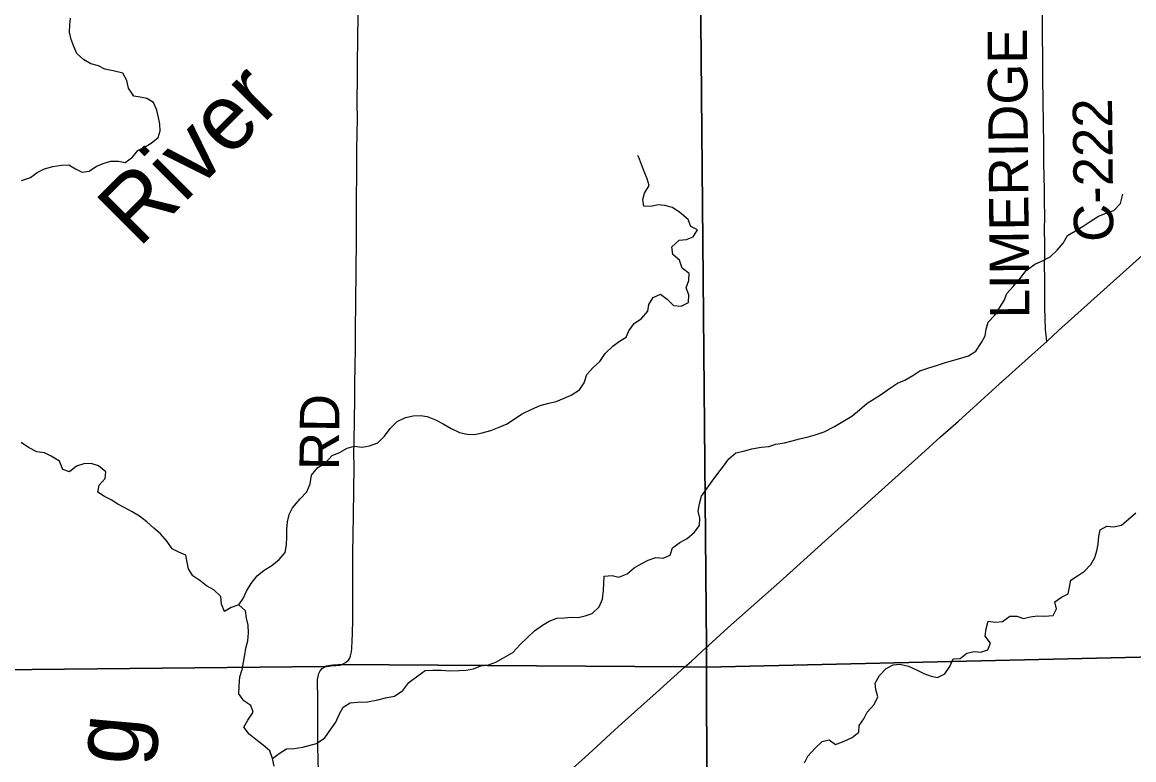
# Model space of a CAD drawing. Extents: x 0 to 34, y 0 to 22.
# Drawn here: x 26.924 to 28.527, y 12.614 to 13.678 of the extents above; entities that cross this region are included whole.
import ezdxf

# ---------------------------------------------------------------- set-up
doc = ezdxf.new("R2010")
doc.units = 0
for name, color, linetype in [('GM_X_Corporation', 7, 'Continuous'), ('GM_X_County_Road', 7, 'Continuous'), ('GM_X_County_Road_Text', 7, 'Continuous'), ('GM_X_Minor_River', 7, 'Continuous'), ('GM_X_Minor_River_Text', 7, 'Continuous'), ('GM_X_State_Route', 7, 'Continuous'), ('GM_X_Township_Road', 7, 'Continuous'), ('GM_X_Township_Road_Text', 7, 'Continuous')]:
    doc.layers.add(name, color=color, linetype=linetype)

msp = doc.modelspace()

# ---------------------------------------------------------------- linework, layer by layer
at = {"layer": 'GM_X_Corporation'}
for points in [[(26.7975, 12.7429), (27.3609, 12.7486), (27.363, 12.7493), (27.3691, 12.7502), (27.3721, 12.7505), (27.377, 12.7508), (27.3825, 12.7513), (27.879, 12.748), (27.9112, 12.7478), (27.9109, 12.7769), (27.9019, 13.7865), (27.8823, 15.2828), (27.8801, 15.6288), (27.88, 15.6409), (27.8849, 16.5038), (27.8821, 16.7067), (23.0715, 16.7067)], [(27.9019, 13.7865), (27.9109, 12.7769), (27.9112, 12.7478), (28.7651, 12.7673)], [(28.7651, 12.7673), (27.9112, 12.7478), (27.9132, 12.0667)], [(27.9132, 12.0667), (27.9112, 12.7478), (27.879, 12.748), (27.3825, 12.7513), (27.377, 12.7508), (27.3721, 12.7505), (27.3691, 12.7502), (27.363, 12.7493), (27.3609, 12.7486), (26.7975, 12.7429)]]:
    msp.add_lwpolyline(points, dxfattribs=at)
at = {"layer": 'GM_X_County_Road'}
msp.add_lwpolyline([(28.402, 13.2172), (28.4007, 13.2265), (28.3999, 13.2346), (28.3993, 13.2511), (28.399, 13.266), (28.3989, 13.2847), (28.3987, 13.3002), (28.3987, 13.307), (28.3986, 13.3282), (28.3987, 13.3412), (28.3988, 13.3586), (28.3986, 13.3784), (28.3988, 13.3975), (28.3986, 13.4198), (28.3983, 13.4359), (28.3977, 13.475), (28.3975, 13.4886), (28.3975, 13.5017), (28.3966, 13.5629), (28.396, 13.5979), (28.3958, 13.6141), (28.3957, 13.6713), (28.3952, 13.7432)], dxfattribs=at)
at = {"layer": 'GM_X_Minor_River'}
for points in [[(27.1006, 13.4972), (27.1104, 13.5034), (27.1202, 13.5115), (27.1231, 13.521), (27.1226, 13.5305), (27.121, 13.5404), (27.1186, 13.5506), (27.1139, 13.5619), (27.104, 13.5675), (27.0945, 13.5697), (27.0851, 13.5711), (27.0774, 13.5824), (27.0753, 13.5937), (27.0695, 13.6043), (27.0555, 13.6076), (27.0437, 13.6101), (27.0342, 13.6149), (27.0232, 13.6178), (27.0129, 13.6238), (27.0033, 13.6324), (26.999, 13.6426), (26.9951, 13.6528), (26.9927, 13.6634), (26.993, 13.6737), (26.994, 13.6835)], [(26.9235, 13.4496), (26.9364, 13.4539), (26.9461, 13.4608), (26.9567, 13.4663), (26.9684, 13.4695), (26.9812, 13.4715), (26.9915, 13.472), (27.001, 13.4664), (27.0109, 13.4612), (27.0207, 13.4629), (27.0313, 13.4698), (27.0426, 13.4745), (27.0524, 13.4773), (27.0634, 13.477), (27.0729, 13.4752), (27.0834, 13.483), (27.0909, 13.4925), (27.1006, 13.4972)], [(27.2368, 12.8374), (27.2431, 12.8469), (27.2479, 12.8572), (27.2543, 12.8683), (27.2632, 12.8794), (27.2734, 12.8875), (27.2843, 12.8941), (27.2948, 12.903), (27.3037, 12.913), (27.3055, 12.924), (27.3058, 12.9358), (27.306, 12.9468), (27.307, 12.957), (27.3092, 12.9677), (27.314, 12.9776), (27.3252, 12.9903), (27.3346, 13.0006), (27.3394, 13.0121), (27.3415, 13.0243), (27.3505, 13.0354), (27.3618, 13.0424), (27.3711, 13.0527), (27.382, 13.0574), (27.393, 13.0636), (27.4028, 13.0664), (27.4145, 13.065), (27.4251, 13.067), (27.4372, 13.0713), (27.4466, 13.0809), (27.4548, 13.0917), (27.4649, 13.1017), (27.4769, 13.1075), (27.4879, 13.1099), (27.4989, 13.1104), (27.5084, 13.109), (27.5205, 13.1042), (27.5312, 13.0983), (27.543, 13.092), (27.5548, 13.086), (27.5662, 13.0835), (27.5764, 13.0832), (27.5878, 13.0856), (27.5999, 13.0888), (27.6119, 13.0939), (27.6236, 13.0986), (27.6341, 13.1056), (27.6454, 13.1129), (27.659, 13.1199), (27.671, 13.125), (27.6839, 13.1282), (27.6945, 13.1306), (27.7058, 13.1353), (27.7159, 13.1399), (27.728, 13.1477), (27.7347, 13.1576), (27.7383, 13.1698), (27.7477, 13.1798), (27.7574, 13.1886), (27.7649, 13.2001), (27.7758, 13.2105), (27.7855, 13.2178), (27.7953, 13.2233), (27.799, 13.2328), (27.8068, 13.2431), (27.8173, 13.2505), (27.8263, 13.2612), (27.8277, 13.2707), (27.8341, 13.2807), (27.8446, 13.2854), (27.8542, 13.2783), (27.8637, 13.2693), (27.8747, 13.2683), (27.8853, 13.2737), (27.8855, 13.2847), (27.8816, 13.2945), (27.8857, 13.3052), (27.8859, 13.3155), (27.876, 13.3229), (27.8721, 13.3343), (27.8625, 13.3425), (27.8609, 13.3535), (27.8718, 13.3631), (27.882, 13.3644), (27.8918, 13.3683), (27.8981, 13.3783), (27.8886, 13.3831), (27.8847, 13.3933), (27.8725, 13.4034), (27.8621, 13.4105), (27.8511, 13.4134), (27.8413, 13.4141), (27.8307, 13.412), (27.8205, 13.4123), (27.8192, 13.4218), (27.8218, 13.4313), (27.8285, 13.442), (27.8253, 13.4518), (27.821, 13.4624), (27.8171, 13.4722), (27.8128, 13.484), (27.8117, 13.4855)], [(28.2993, 13.2034), (28.3078, 13.2156), (28.313, 13.2256), (28.3144, 13.2351), (28.317, 13.245), (28.3267, 13.2554), (28.3334, 13.2657), (28.3405, 13.2764), (28.3442, 13.2863), (28.3531, 13.2963), (28.3629, 13.3078), (28.3722, 13.3197), (28.3846, 13.3286), (28.3948, 13.3332), (28.4068, 13.3395), (28.4166, 13.3491), (28.4255, 13.3591), (28.4315, 13.3701), (28.4431, 13.3767), (28.454, 13.3837), (28.4642, 13.3903), (28.4762, 13.398), (28.4872, 13.4023), (28.4985, 13.4062), (28.5078, 13.4162), (28.5111, 13.4277), (28.5115, 13.4296)], [(27.2851, 12.6162), (27.2949, 12.6232), (27.3054, 12.6297), (27.3164, 12.6306), (27.3292, 12.6323), (27.3489, 12.6378), (27.3605, 12.6459), (27.3695, 12.6582), (27.3766, 12.6685), (27.3814, 12.6792), (27.3873, 12.6899), (27.3975, 12.6965), (27.4077, 12.697), (27.4224, 12.6979), (27.4372, 12.7008), (27.4481, 12.7035), (27.461, 12.706), (27.4734, 12.7141), (27.482, 12.7256), (27.4947, 12.7352), (27.5056, 12.743), (27.5166, 12.7435), (27.5284, 12.7432), (27.5409, 12.7422), (27.5545, 12.7431), (27.5643, 12.7433), (27.5749, 12.7453), (27.5859, 12.7496), (27.5968, 12.7509), (27.6074, 12.7548), (27.6183, 12.761), (27.6319, 12.7687), (27.6423, 12.7806), (27.6532, 12.7906), (27.6629, 12.7999), (27.6746, 12.8084), (27.6844, 12.8138), (27.6953, 12.8185), (27.7063, 12.8186), (27.7161, 12.8199), (27.726, 12.8192), (27.7362, 12.8216), (27.746, 12.8251), (27.7561, 12.8348), (27.7613, 12.8458), (27.7626, 12.8584), (27.7629, 12.8682), (27.7636, 12.8789), (27.7749, 12.8798), (27.7848, 12.8776), (27.7965, 12.8823), (27.8066, 12.8908), (27.8168, 12.8966), (27.8269, 12.902), (27.8379, 12.9056), (27.8485, 12.9049), (27.8587, 12.9092), (27.8619, 12.9199), (27.8728, 12.9276), (27.883, 12.9334), (27.8935, 12.9419), (27.901, 12.9519), (27.9016, 12.9625), (27.8989, 12.9727), (27.901, 12.9834), (27.9039, 12.9944), (27.9121, 13.0056), (27.9192, 13.0159), (27.9274, 13.027), (27.9356, 13.0377), (27.9435, 13.0481), (27.9532, 13.0565), (27.9645, 13.059), (27.9762, 13.0625), (27.9899, 13.0649), (28.0008, 13.0658), (28.011, 13.069), (28.0235, 13.071), (28.0344, 13.0738), (28.0454, 13.077), (28.0575, 13.0798), (28.0677, 13.0826), (28.0805, 13.0869), (28.0956, 13.0947), (28.1099, 13.1032), (28.1204, 13.1098), (28.1317, 13.1186), (28.1425, 13.1283), (28.1527, 13.1348), (28.1632, 13.1414), (28.1764, 13.1503), (28.1865, 13.1573), (28.1971, 13.1616), (28.2088, 13.1682), (28.2189, 13.1747), (28.2302, 13.179), (28.2442, 13.183), (28.2559, 13.1869), (28.2778, 13.1933), (28.2887, 13.1968), (28.2993, 13.2034)], [(27.2259, 12.8338), (27.2161, 12.828), (27.2118, 12.8386), (27.2109, 12.8496), (27.2006, 12.8593), (27.1899, 12.8649), (27.1804, 12.8728), (27.1704, 12.8795), (27.1643, 12.8893), (27.1623, 12.8991), (27.1602, 12.909), (27.15, 12.9134), (27.1405, 12.9182), (27.1335, 12.9288), (27.1239, 12.9401), (27.114, 12.9483), (27.104, 12.9573), (27.0937, 12.9652), (27.0827, 12.9715), (27.0724, 12.9774), (27.0621, 12.9826), (27.0525, 12.989), (27.043, 12.9938), (27.0335, 12.9998), (27.0353, 13.01), (27.0442, 13.0196), (27.0449, 13.0291), (27.0346, 13.0381), (27.0236, 13.0414), (27.013, 13.0409), (27.0028, 13.0377), (26.9926, 13.0293), (26.9831, 13.0326), (26.9781, 13.0447), (26.9662, 13.0517), (26.9563, 13.0566), (26.9457, 13.0583), (26.9335, 13.0643), (26.9228, 13.0717)], [(28.1527, 12.694), (28.1583, 12.7051), (28.1551, 12.7153), (28.1543, 12.7248), (28.1606, 12.7355), (28.1699, 12.7458), (28.1801, 12.7509), (28.1899, 12.7518), (28.2021, 12.7493), (28.2139, 12.7437), (28.2242, 12.7385), (28.2348, 12.7348), (28.2443, 12.733), (28.2545, 12.7381), (28.2619, 12.7488), (28.2667, 12.7595), (28.2766, 12.7604), (28.2863, 12.7681), (28.2969, 12.7705), (28.3064, 12.7691), (28.3166, 12.7726), (28.3206, 12.7822), (28.3129, 12.7923), (28.3143, 12.803), (28.3172, 12.814), (28.3279, 12.8126), (28.3377, 12.8135), (28.3486, 12.8212), (28.3585, 12.8213), (28.368, 12.8177), (28.3778, 12.8204), (28.3884, 12.8217), (28.3982, 12.8214), (28.4111, 12.8223), (28.4155, 12.8319), (28.4131, 12.8417), (28.4229, 12.8487), (28.4327, 12.8534), (28.4345, 12.8629), (28.4363, 12.8731), (28.446, 12.8793), (28.4562, 12.8859), (28.4652, 12.8959), (28.4711, 12.9058), (28.474, 12.9153), (28.4758, 12.9249), (28.4769, 12.9359), (28.4786, 12.9458), (28.4884, 12.9512), (28.4979, 12.9502), (28.5096, 12.9522), (28.5194, 12.9611), (28.5299, 12.9703)], [(27.2875, 12.6048), (27.2851, 12.6162), (27.2812, 12.6272), (27.2716, 12.6354), (27.2613, 12.6436), (27.2514, 12.6511), (27.2441, 12.6613), (27.2497, 12.6712), (27.2575, 12.6827), (27.254, 12.6925), (27.244, 12.6992), (27.2367, 12.709), (27.2374, 12.7204), (27.238, 12.7337), (27.2413, 12.7444), (27.2434, 12.7547), (27.2452, 12.7653), (27.2466, 12.7752), (27.2495, 12.7855), (27.2505, 12.7973), (27.2504, 12.8083), (27.2476, 12.8185), (27.2464, 12.8287), (27.2368, 12.8374), (27.2259, 12.8338)], [(28.0525, 12.6097), (28.0573, 12.6196), (28.0674, 12.6303), (28.0779, 12.6407), (28.0878, 12.6431), (28.0973, 12.6364), (28.1094, 12.6411), (28.121, 12.6465), (28.1308, 12.6539), (28.1311, 12.6634), (28.1378, 12.6733), (28.1426, 12.6829), (28.1527, 12.694)]]:
    msp.add_lwpolyline(points, dxfattribs=at)
at = {"layer": 'GM_X_State_Route'}
msp.add_line((27.9111, 12.7764), (27.9134, 12.7784), dxfattribs=at)
for points in [[(27.9134, 12.7784), (27.9425, 12.8048), (28.0163, 12.8703), (28.0564, 12.9065), (28.0822, 12.9299), (28.1233, 12.967), (28.1543, 12.9947), (28.1926, 13.0293), (28.2212, 13.0546), (28.2487, 13.0796), (28.2746, 13.1026), (28.3064, 13.1315), (28.3331, 13.1557), (28.3803, 13.1979), (28.402, 13.2172), (28.4187, 13.2331), (28.5256, 13.329), (28.6314, 13.424), (28.6966, 13.4835), (28.793, 13.5705), (28.8606, 13.6316), (28.8818, 13.6509), (28.9186, 13.6843)], [(27.8792, 12.7475), (27.8892, 12.7565), (27.9111, 12.7764)], [(27.6966, 12.5826), (27.7354, 12.6175), (27.7588, 12.6388), (27.7726, 12.6514), (27.7897, 12.6668), (27.8386, 12.7109), (27.8792, 12.7475)]]:
    msp.add_lwpolyline(points, dxfattribs=at)
at = {"layer": 'GM_X_Township_Road'}
for points in [[(27.3827, 12.7508), (27.3873, 12.7526), (27.3905, 12.7542), (27.395, 12.7577), (27.3966, 12.7606), (27.3979, 12.7642), (27.3991, 12.7698), (27.3997, 12.7748), (27.4, 12.7861), (27.4004, 12.7954), (27.4009, 12.8171), (27.401, 12.8314), (27.4009, 12.8582), (27.4011, 12.8737), (27.4011, 12.888), (27.4011, 12.8979), (27.4012, 12.9028), (27.4013, 12.9078), (27.4013, 12.9115), (27.4014, 12.9401), (27.4019, 12.9649), (27.4025, 13.0042), (27.403, 13.0357), (27.4026, 13.0569), (27.4028, 13.0718), (27.4034, 13.1053), (27.4039, 13.1328), (27.4042, 13.1576), (27.4045, 13.1796), (27.4048, 13.2091), (27.4049, 13.2447), (27.4052, 13.2628), (27.4054, 13.2826), (27.406, 13.3105), (27.4061, 13.3282), (27.4063, 13.3542), (27.4066, 13.3718), (27.4066, 13.3811), (27.4066, 13.3966), (27.4064, 13.4096), (27.4065, 13.4301), (27.4069, 13.4524), (27.407, 13.4804), (27.4071, 13.4996), (27.4072, 13.5113), (27.4073, 13.52), (27.4077, 13.5356), (27.4074, 13.5636), (27.4076, 13.5979), (27.4079, 13.6201), (27.4084, 13.6505), (27.4086, 13.6897)], [(27.3515, 12.5974), (27.3511, 12.6154), (27.3506, 12.6329), (27.3506, 12.6506), (27.3508, 12.6679), (27.3505, 12.6799), (27.3505, 12.6981), (27.3504, 12.7108), (27.3502, 12.7187), (27.3503, 12.7299), (27.3509, 12.7341), (27.3522, 12.7387), (27.3539, 12.7426), (27.3571, 12.7458), (27.3611, 12.7481)], [(27.3611, 12.7481), (27.3632, 12.7487), (27.3693, 12.7496), (27.3723, 12.7499), (27.3772, 12.7503), (27.3827, 12.7508)]]:
    msp.add_lwpolyline(points, dxfattribs=at)

# ---------------------------------------------------------------- texts
at = {"layer": 'GM_X_County_Road_Text'}
for s, rotation, p in [('LIMERIDGE', 90.4971, (28.3767, 13.2508)), ('C-222', 90.55, (28.4978, 13.3611))]:
    msp.add_text(s, height=0.05682, rotation=rotation, dxfattribs=at).set_placement(p)
at = {"layer": 'GM_X_Minor_River_Text'}
for s, height, rotation, p in [('River', 0.09475, 44.9725, (27.0923, 13.351)), ('Mahoning', 0.09473, 84.9771, (27.047, 12.1208))]:
    msp.add_text(s, height=height, rotation=rotation, dxfattribs=at).set_placement(p)
at = {"layer": 'GM_X_Township_Road_Text'}
msp.add_text('RD', height=0.05682, rotation=89.5136, dxfattribs=at).set_placement((27.3809, 13.0315))

doc.saveas('drawing.dxf')
